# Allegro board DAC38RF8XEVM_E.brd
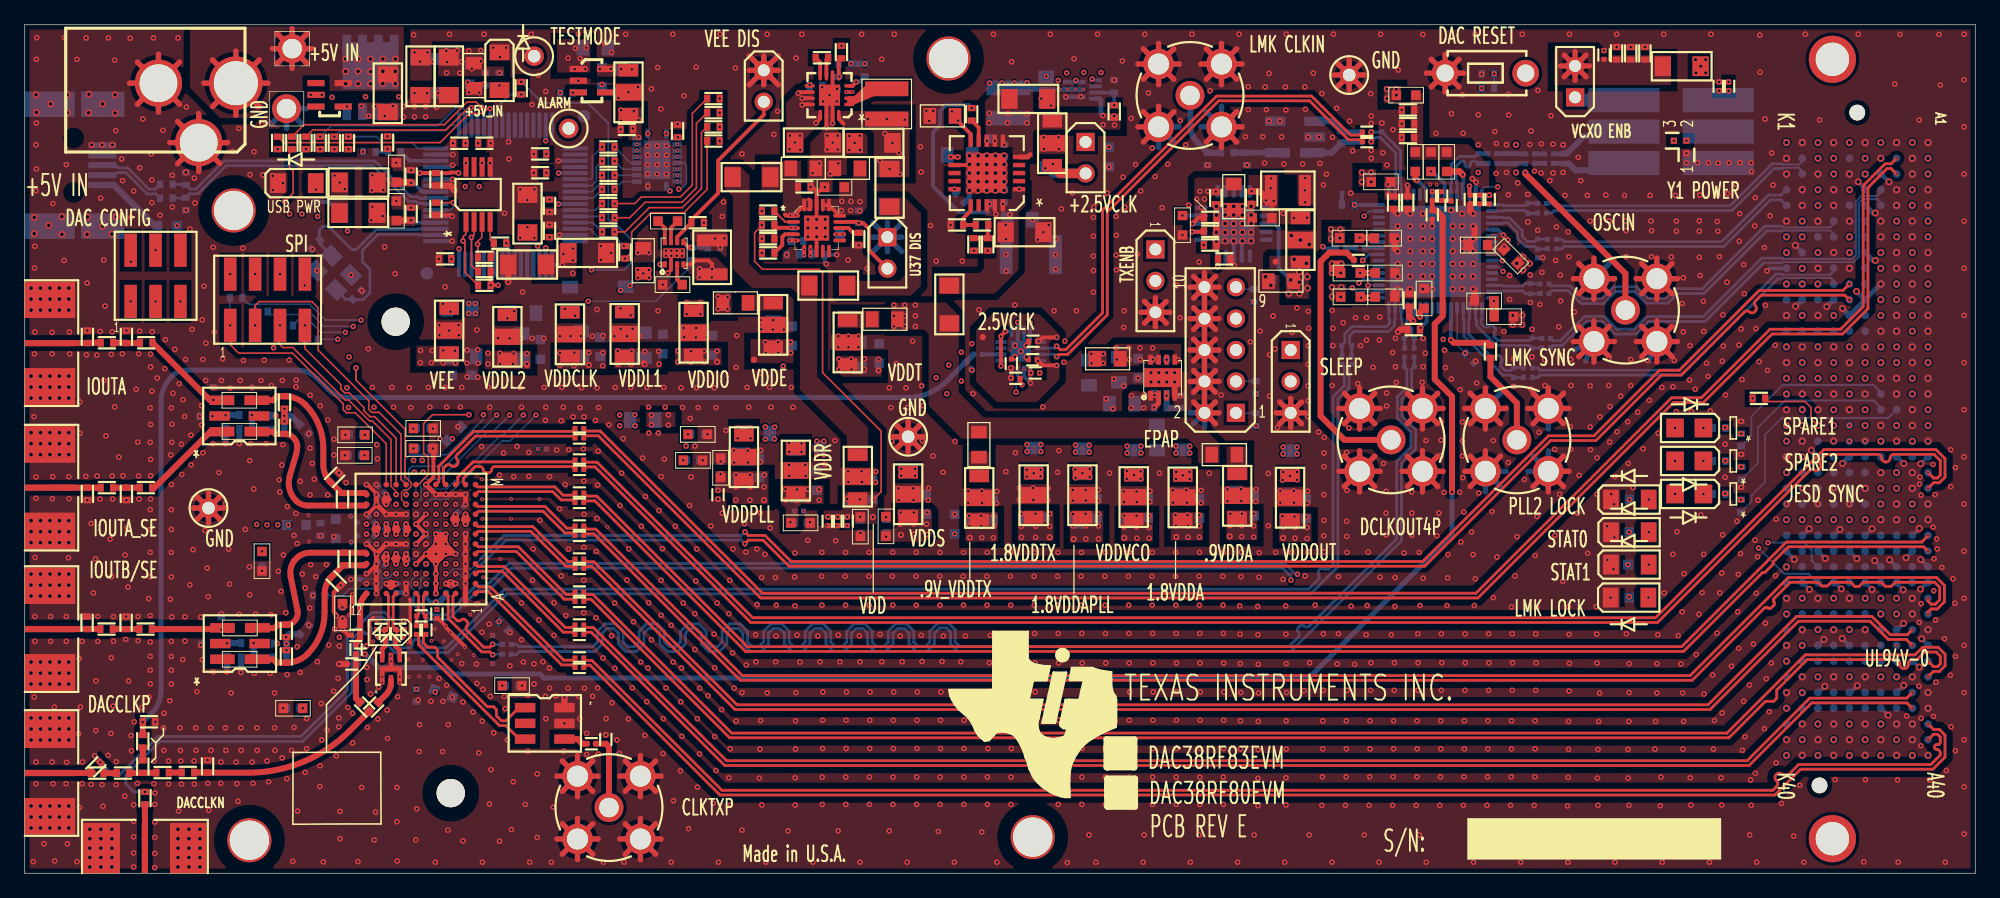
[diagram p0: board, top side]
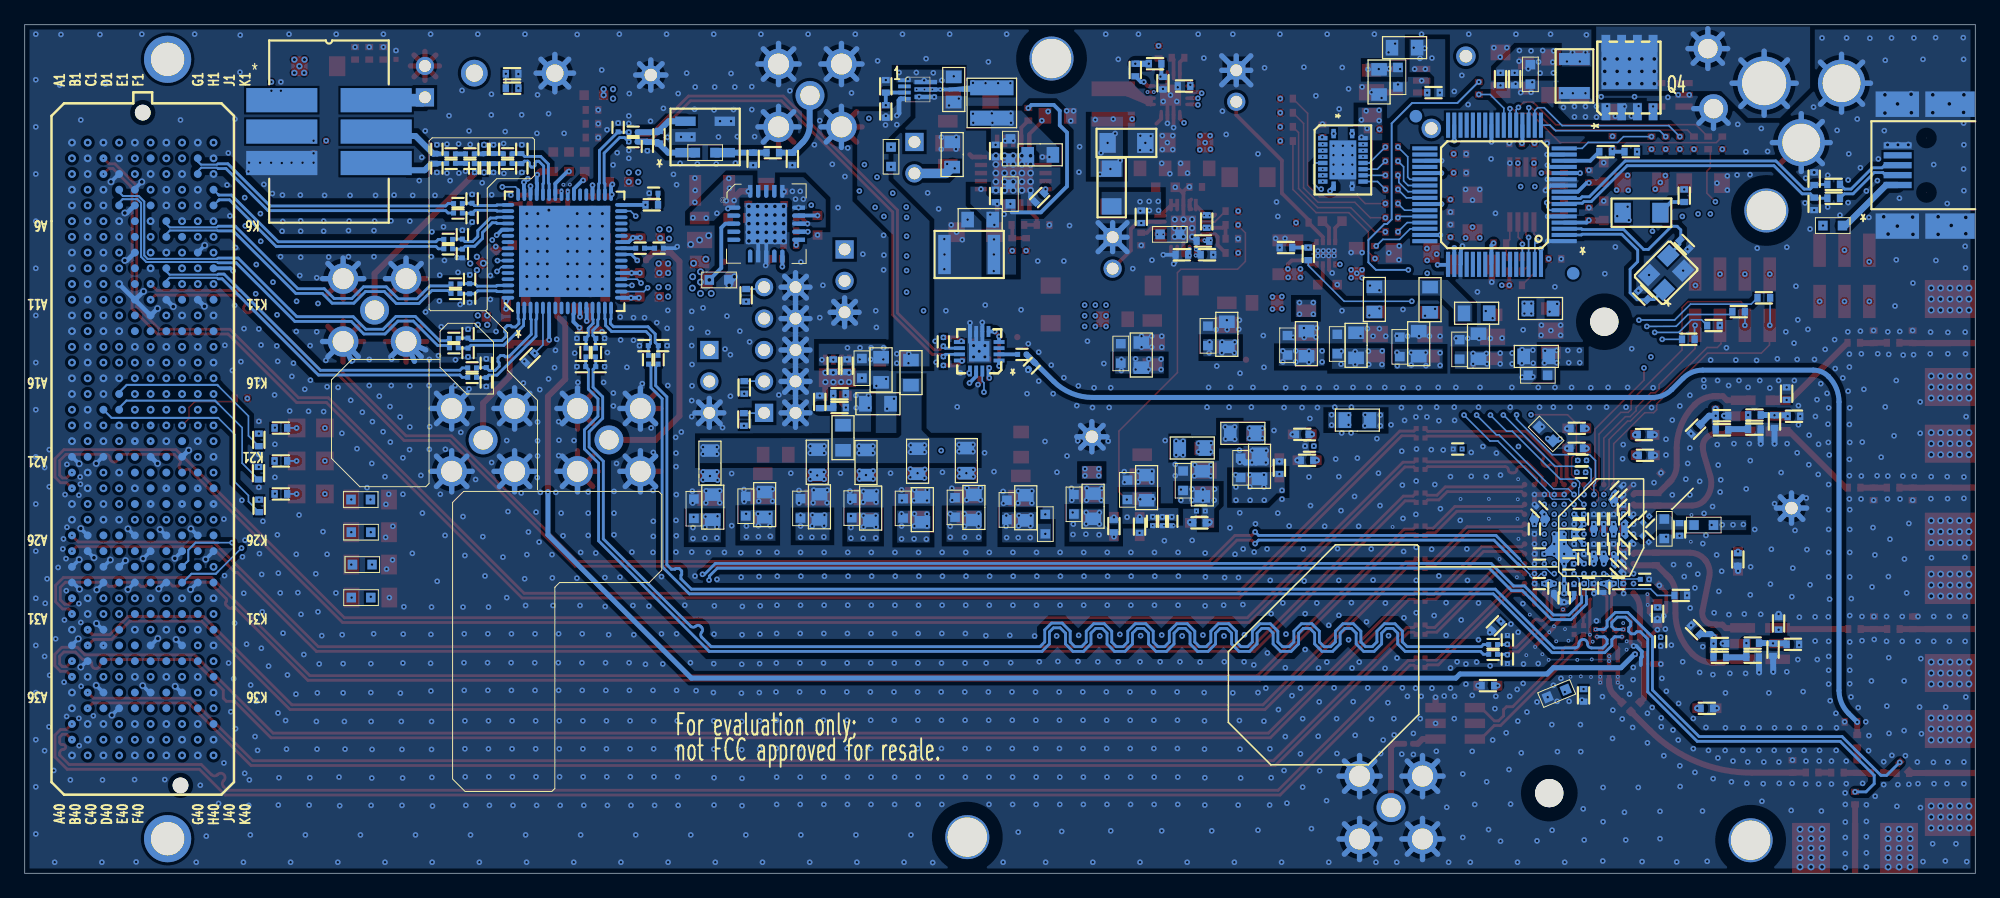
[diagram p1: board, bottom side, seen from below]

Outline 157.48 x 68.58 mm; copper layers: TOP, L2_GND, L3_PWR, L4_SIG, L5_GND, L6_PWR_SIG, L7_GND, BOTTOM. Coordinates in mm from the lower left corner of the outline.
Outline path: 0,68.58 0,0 157.48,0 157.48,68.58 0,68.58

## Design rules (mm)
net group CAR_SYSREF: nets CAR_SYSREFM CAR_SYSREFP
net group CLK: nets CLKN CLKP
net group CLK_LAO: nets CLK_LAO_0M CLK_LAO_0P
net group CLKIN1: nets CLKIN1_N CLKIN1_P
net group DIFFPAIR0: nets DP0_C2M_N_A DP0_C2M_P_A
net group DIFFPAIR1: nets DP7_C2M_N_A DP7_C2M_P_A
net group DIFFPAIR2: nets DP1_C2M_N_A DP1_C2M_P_A
net group DIFFPAIR3: nets DP2_C2M_N_A DP2_C2M_P_A
net group DIFFPAIR4: nets DP3_C2M_N_A DP3_C2M_P_A
net group DIFFPAIR5: nets DP4_C2M_N_A DP4_C2M_P_A
net group DIFFPAIR6: nets DP5_C2M_N_A DP5_C2M_P_A
net group DIFFPAIR7: nets DP6_C2M_N_A DP6_C2M_P_A
net group DIFFPAIR9: nets GTXCLKM GTXCLKP
net group DIFFPAIR12: nets FPGA_CLK1N FPGA_CLK1P
net group DIFFPAIR13: nets FPGA_CLK1_N FPGA_CLK1_P
net group DIFFPAIR14: nets FPGA_CLK2N FPGA_CLK2P
net group DIFFPAIR15: nets FPGA_CLK2_N FPGA_CLK2_P
net group DP1: nets DM DP
net group DP2: nets CLKLA_0M CLKLA_0P
net group DP3: nets CAR_SYSREF_M CAR_SYSREF_P
net group DP4: nets DACCLK_N DACCLK_P
net group DP5: nets SYSREF+ SYSREF-
net group DP6: nets N19086842 N19086844
net group DP7: nets OSCI OSCO
net group DP8: nets N18276385 N18276388
net group DP9: nets N17929635 N17930866
net group DP10: nets N18336017 N18336019
net group DP11: nets N18681043 N18681093
net group DP12: nets N18858975 N18893766
net group GTX_CLK: nets GTX_CLKM GTX_CLKP
net group OSC: nets OSCN OSCP
net group OSCIN: nets OSCINN OSCINP
net group RX0: nets RX0N RX0P
net group RX1: nets RX1N RX1P
net group RX2: nets RX2N RX2P
net group RX3: nets RX3N RX3P
net group RX4: nets RX4N RX4P
net group RX5: nets RX5N RX5P
net group RX6: nets RX6N RX6P
net group RX7: nets RX7N RX7P
net group SYNC0B: nets SYNC0BN SYNC0BP
net group SYNC1B: nets SYNC1BN SYNC1BP
net group SYSREF: nets SYSREFN SYSREFP
net group SYSREF-: nets SYSREF-N SYSREF-P
net group USB_M: nets USB_DM USB_DP
net group Y2: nets Y2_N Y2_P

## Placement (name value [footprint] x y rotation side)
C1  0.01uF  [0402]  28.16 13.43 45 top
C2  .1uF  [0201]  28.77 19.36 45 top
C3  .1uF  [0201]  30.29 19.36 135 top
C5  .1uF  [0201]  44.78 24.64 180 top
C6  .1uF  [0201]  44.78 25.4 180 top
C8  .1uF  [0201]  44.78 19.3 180 top
C9  .1uF  [0201]  44.78 20.07 180 top
C10  .1uF  [0201]  44.78 17.4 180 top
C11  .1uF  [0201]  44.78 16.64 180 top
C13  .1uF  [0201]  44.78 22.73 180 top
C14  .1uF  [0201]  44.78 21.97 180 top
C16  .1uF  [0201]  44.78 27.3 180 top
C17  .1uF  [0201]  44.78 28.07 180 top
C18  .1uF  [0201]  44.78 29.97 180 top
C19  .1uF  [0201]  44.78 30.73 180 top
C21  .1uF  [0201]  44.78 33.4 180 top
C22  .1uF  [0201]  44.78 32.64 180 top
C23  .1uF  [0201]  44.78 35.94 180 top
C24  .1uF  [0201]  44.78 35.18 180 top
C25  0.01uF  [0201]  27.1 17.7 0 top
C27  .001uF  [0402]  118.13 64.62 180 bottom
C28  .1uF  [0201]  26.68 23.76 180 bottom
C29  .1uF  [0201]  122.83 43.23 0 bottom
C30  .68uF  [0402]  106.86 54.03 180 bottom
C31  .1uF  [0201]  136.8 63.6 90 top
C32  .1uF  [0201]  122.83 42.47 0 bottom
C33  3900pF  [0201]  117.47 54.46 270 top
C34  47pF  [0201]  116.71 54.46 270 top
C35  .1uF  [0201]  108.36 59.13 0 bottom
C36  .1uF  [0201]  108.36 59.89 0 bottom
C37  .1uF  [0201]  109.57 60.28 270 bottom
C38  .1uF  [0201]  127.51 66.14 270 top
C39  100pF  [0402]  128.52 66.27 270 top
C40  2200pF  [0402]  129.67 66.27 270 top
C41  10pF  [0402]  130.81 66.27 270 top
C42  .1uF  [0201]  123.29 51.23 0 bottom
C43  .1uF  [0201]  123.29 50.47 0 bottom
C44  .1uF  [0201]  121.54 58.14 180 bottom
C45  .1uF  [0201]  118.49 58.14 180 bottom
C46  .1uF  [0201]  117.35 58.52 270 bottom
C47  .1uF  [0201]  122.5 54.13 0 bottom
C48  .1uF  [0201]  122.5 53.37 0 bottom
C49  .1uF  [0201]  121.54 57.38 180 bottom
C50  .1uF  [0201]  118.49 57.38 180 bottom
C51  12pF  [0201]  117.35 57 90 bottom
C52  1uF  [0402]  110.52 54.2 90 top
C53  .1uF  [0402]  111.66 54.2 90 top
C54  0.01uF  [0402]  112.14 43.94 0 top
C55  1uF  [0603]  109.83 46.58 180 top
C56  1uF  [0603]  109.83 48.51 180 top
C57  1uF  [0603]  109.75 51.33 180 top
C58  1uF  [0402]  111.68 61.7 0 top
C59  .1uF  [0402]  111.68 60.58 0 top
C60  0.01uF  [0402]  111.68 59.46 0 top
C61  .1uF  [0402]  111.79 46.3 90 top
C62  10uF  [0603]  112.98 46.46 90 top
C63  1uF  [0603]  117.32 50.77 0 top
C64  1uF  [0603]  117.83 46.25 0 top
C65  .1uF  [0402]  31.19 56.31 90 top
C66  4.7uF  [0603]  30 56.64 90 top
C67  .1uF  [0402]  31.19 53.29 90 top
C68  4.7uF  [0603]  30 53.54 90 top
C70  10uF  [0805]  46.08 66.73 0 bottom
C71  1.0uF  [0603]  46.61 64.34 270 bottom
C72  10uF  [0805]  48.13 63.96 270 bottom
C73  100uF  [1206]  40.59 53.31 90 top
C74  10uF  [1206]  45.42 50.14 0 top
C75  100uF  [1206]  40.56 49.2 180 top
C76  22pF  [0402]  13 56.13 90 bottom
C77  22pF  [0402]  13 54.1 270 bottom
C78  27pF  [0402]  26.84 46.73 45 bottom
C79  27pF  [0402]  23.49 50.81 225 bottom
C80  .1uF  [0402]  35.08 59 0 top
C81  .1uF  [0402]  42.37 51.92 270 top
C82  .1uF  [0402]  41.61 56.62 0 top
C83  .1uF  [0402]  42.37 53.95 90 top
C84  .1uF  [0402]  33.93 49.66 0 top
C85  .1uF  [0402]  41.61 58.14 0 top
C86  .1uF  [0402]  33.2 56.08 90 top
C87  .1uF  [0402]  37.11 59 180 top
C106  10uF  [0603]  53.95 33.38 0 top
C107  .1uF  [0201]  41.78 34.29 0 bottom
C108  .1uF  [0201]  35.2 29.41 45 bottom
C110  10uF  [0603]  32.17 34.33 0 top
C111  .1uF  [0201]  31.74 33.37 180 bottom
C112  .1uF  [0201]  30.8 28.63 90 bottom
C114  10uF  [0603]  67.46 28.02 270 top
C115  .1uF  [0201]  33.28 20.96 270 top
C116  .1uF  [0201]  66.4 28.45 270 top
C117  .1uF  [0201]  32.81 25 180 bottom
C118  .1uF  [0201]  33.19 22.26 270 bottom
C119  10uF  [0603]  34.65 35.51 45 bottom
C120  1uF  [0201]  32 28.24 180 bottom
C122  .1uF  [0201]  31.6 25.4 90 bottom
C123  .1uF  [0201]  65.63 28.45 270 bottom
C124  .1uF  [0201]  65.63 28.45 270 top
C125  .1uF  [0201]  31.98 29.01 180 bottom
C126  .1uF  [0201]  64.87 28.45 270 bottom
C127  .1uF  [0201]  35.18 25.81 0 bottom
C128  .1uF  [0201]  66.42 28.45 270 bottom
C129  .1uF  [0201]  64.87 28.45 270 top
C131  10uF  [0603]  26.64 33.78 180 top
C132  .1uF  [0201]  29.2 26.99 270 bottom
C133  .1uF  [0201]  29.22 28.63 90 bottom
C135  10uF  [0603]  32.17 35.96 0 top
C136  .1uF  [0201]  30.01 28.63 90 bottom
C137  .1uF  [0201]  31.81 32.41 0 bottom
C139  10uF  [0603]  25.65 21.01 270 top
C140  .1uF  [0201]  28.4 29.4 90 bottom
C141  .1uF  [0201]  28.38 26.21 270 bottom
C143  10uF  [0603]  56.18 32.77 90 top
C144  .1uF  [0201]  55.97 30.59 270 top
C145  .1uF  [0201]  30.8 26.23 90 bottom
C147  10uF  [0603]  19.15 25.22 270 top
C148  .1uF  [0201]  27.99 27.01 225 bottom
C149  .1uF  [0201]  28 28.6 135 bottom
C151  10uF  [0603]  25.11 27.84 270 bottom
C152  .1uF  [0201]  26.61 27.01 225 bottom
C153  .1uF  [0201]  26.57 28.6 135 bottom
C155  10uF  [0603]  21.66 13.34 180 top
C156  .1uF  [0201]  30.01 26.23 90 bottom
C157  .1uF  [0201]  25.4 18.72 270 bottom
C159  10uF  [0603]  33.79 14.53 337.5 bottom
C160  .1uF  [0201]  28.81 23.41 180 bottom
C161  .1uF  [0201]  29.99 23.05 270 bottom
C163  10uF  [0603]  26.67 35.44 180 top
C164  .1uF  [0201]  28.8 25.42 225 bottom
C165  .1uF  [0201]  28.79 31.03 135 bottom
C167  .1uF  [0201]  35.2 23.41 0 bottom
C168  10uF  [0603]  54.34 35.47 0 top
C169  .1uF  [0201]  53.76 34.53 0 bottom
C170  .1uF  [0201]  31.21 23.41 180 bottom
C171  .1uF  [0201]  34.02 23.04 270 bottom
C174  .1uF  [0201]  35.59 27.82 270 bottom
C175  .1uF  [0201]  62.52 29.28 0 bottom
C176  .1uF  [0201]  28.82 24.63 225 bottom
C177  .1uF  [0201]  28.8 30.21 135 bottom
C179  .1uF  [0402]  22.58 19.69 45 bottom
C218  10uF  [0603]  69.53 28.04 90 top
C220  10uF  [0603]  62.64 28.32 0 top
C221  47uF  [1210]  32.36 64.44 90 bottom
C222  10uF  [0805]  36.27 64.47 270 top
C223  .1uF  [0402]  37.19 64.19 90 bottom
C224  22uF  [1206]  31.95 64.41 270 top
C225  1.0uF  [0603]  35.92 64.57 270 bottom
C236  10uF  [0805]  66.9 31.17 90 bottom
C237  1.0uF  [0603]  68.45 30.99 90 bottom
C241  10uF  [0805]  67.34 41.88 90 bottom
C242  1.0uF  [0603]  68.99 42.01 90 bottom
C244  10uF  [0805]  54 42.8 90 bottom
C245  1.0uF  [0603]  55.52 42.67 90 bottom
C247  .1uF  [0402]  79.1 54.74 270 bottom
C248  1.0uF  [0603]  77.9 54.89 90 bottom
C249  33uF  [1812]  81.23 50.01 0 bottom
C250  10uF  [0805]  49.99 42.67 90 bottom
C251  1.0uF  [0603]  51.51 42.77 90 bottom
C253  22uF  [1206]  80.72 51.82 180 top
C254  10uF  [0805]  80.34 52.83 0 bottom
C255  10uF  [0805]  71.22 29.67 90 bottom
C256  1.0uF  [0603]  72.77 29.82 90 bottom
C258  10uF  [0805]  75.49 58.06 0 bottom
C259  1.0uF  [0603]  77.9 58.57 270 bottom
C260  .1uF  [0402]  79.1 58.37 90 bottom
C262  10uF  [0805]  40.11 42.6 90 bottom
C263  1.0uF  [0603]  41.63 42.34 90 bottom
C268  10uF  [0805]  44.93 42.8 90 bottom
C269  1.0uF  [0603]  46.46 42.55 90 bottom
C271  10uF  [0805]  97.74 29.79 90 bottom
C272  1.0uF  [0603]  99.26 29.67 90 bottom
C274  10uF  [0805]  57.79 32.89 90 bottom
C275  1.0uF  [0603]  59.31 32.77 90 bottom
C282  10uF  [0805]  93.32 29.62 90 bottom
C283  1.0uF  [0603]  94.84 29.49 90 bottom
C291  10uF  [0805]  101.93 29.59 90 bottom
C292  1.0uF  [0603]  103.45 29.46 90 bottom
C294  10uF  [0805]  89.18 29.51 90 bottom
C295  1.0uF  [0603]  90.7 29.51 90 bottom
C300  10uF  [0805]  49.94 49.5 90 top
C303  47uF  [1210]  55.5 49.78 90 top
C304  10uF  [0805]  85.01 29.39 90 bottom
C305  1.0uF  [0603]  86.56 29.49 90 bottom
C307  1.0uF  [0603]  51.92 52.7 180 top
C308  10uF  [0805]  62.41 31.47 90 bottom
C309  1.0uF  [0603]  63.96 31.72 90 bottom
C311  10uF  [0805]  97.61 54.69 270 top
C312  .1uF  [0402]  95.71 53.01 180 top
C313  0.01uF  [0402]  96.16 54.58 90 top
C314  .1uF  [0402]  99.06 54.61 270 top
C315  1.0uF  [0603]  99.9 52.96 180 top
C316  47uF  [1210]  101.98 55.19 0 top
C317  10uF  [0805]  101.42 47.85 180 top
C318  1.0uF  [0603]  101.42 47.96 180 bottom
C320  1.0uF  [0603]  93.47 52.37 270 top
C321  1.0uF  [0603]  35.31 40.25 0 bottom
C322  10uF  [0805]  35.44 41.77 0 bottom
C327  5600pF  [0402]  14.72 18.5 180 bottom
C328  .3pF  [0402]  15.88 20.19 90 bottom
C329  5600pF  [0402]  9.75 19.74 180 top
C330  1000pF  [0402]  17.97 18.6 180 bottom
C331  1000pF  [0402]  16.32 18.07 90 bottom
C332  1000pF  [0402]  17.97 17.46 0 bottom
C333  0.01uF  [0201]  29.12 19.36 90 top
C334  0.01uF  [0201]  29.94 19.36 90 top
C342  1uF  [0402]  53.95 33.38 180 bottom
C343  1uF  [0402]  32.17 35.97 180 bottom
C344  1uF  [0402]  56.18 32.77 270 bottom
C345  1uF  [0402]  32.18 34.35 180 bottom
C346  1uF  [0402]  67.47 28.02 90 bottom
C347  1uF  [0402]  26.66 33.78 0 bottom
C348  1uF  [0402]  25.64 20.98 90 bottom
C349  1uF  [0402]  19.17 25.37 90 bottom
C350  1uF  [0402]  23.88 27.79 90 bottom
C351  1uF  [0402]  31.62 14.38 90 bottom
C352  1uF  [0402]  21.67 13.33 0 bottom
C353  1uF  [0402]  54.33 35.48 180 bottom
C356  1uF  [0402]  62.64 28.32 180 bottom
C357  1uF  [0402]  26.75 35.46 0 bottom
C358  1uF  [0402]  69.54 28.06 270 bottom
C360  .1uF  [0201]  113.64 54.74 270 top
C364  .1uF  [0402]  20.62 18.57 0 bottom
C365  .1uF  [0201]  107.67 49.53 180 top
C366  .1uF  [0201]  121.16 57 90 bottom
C368  .1uF  [0402]  48.62 60.12 180 top
C369  .1uF  [0402]  52.71 59.99 270 top
C370  0.01uF  [0402]  27.44 13.44 135 top
C371  .01uF  [0201]  108.36 59.89 0 top
C372  .01uF  [0201]  108.36 59.13 0 top
C373  10uF  [0603]  39.34 15.16 0 top
C374  1uF  [0402]  39.34 15.16 180 bottom
C375  .1uF  [0201]  32.4 22.97 270 bottom
C376  10uF  [0603]  75.08 28.22 90 bottom
C377  1uF  [0402]  38.66 20 135 bottom
C378  .01uF  [0201]  76.96 41.94 0 bottom
C379  .01uF  [0201]  81.58 40.44 0 top
C380  .01uF  [0201]  81.38 41.5 180 top
C381  .01uF  [0201]  79.65 41.2 90 top
C382  .01uF  [0201]  80.01 40.01 0 top
C383  .01uF  [0201]  81.41 43 180 top
C384  22uF  [1206]  63.7 59.05 0 top
C385  0.01uF  [0402]  64.36 65.91 0 top
C386  1.0uF  [0603]  78.18 29.36 90 bottom
C387  10uF  [0805]  76.66 29.54 90 bottom
C388  1.0uF  [0603]  89.89 40.82 270 bottom
C389  .1uF  [0402]  91.08 41.02 90 bottom
C390  10uF  [0805]  88.34 40.69 270 bottom
C391  .047uF  [0402]  92.2 41.02 90 bottom
C392  .047uF  [0402]  91.69 38.76 180 bottom
C393  10uF  [0805]  88.6 37.95 180 bottom
C394  10uF  [0805]  82.47 63.35 270 bottom
C395  22uF  [1206]  81.03 62.59 0 top
C397  5600pF  [0402]  14.63 36.94 180 bottom
C398  .3pF  [0402]  15.23 38.76 90 bottom
C399  5600pF  [0402]  9.8 42.88 180 top
C400  .1uF  [0402]  22.58 35.89 315 bottom
C401  1000pF  [0402]  17.83 37.04 180 bottom
C402  .1uF  [0402]  20.45 36.98 0 bottom
C403  1000pF  [0402]  16.21 36.51 90 bottom
C404  1000pF  [0402]  17.84 35.9 0 bottom
C407  .1uF  [0201]  45.75 10.46 0 top
C413  5600pF  [0402]  9.78 31.17 180 top
C415  10uF  [0805]  74.09 61.21 180 top
C417  1.0uF  [0603]  82.37 29.57 90 bottom
C418  10uF  [0805]  80.85 29.57 90 bottom
C419  1.0uF  [0603]  87.54 57.91 270 bottom
C420  10uF  [0805]  82.6 58.09 90 bottom
C427  0.01uF  [0402]  63.88 63.63 180 bottom
C428  22uF  [1206]  68.53 59.03 180 top
C429  22uF  [1206]  68.53 59.03 180 bottom
C432  1.0uF  [0603]  65.02 51.64 0 bottom
C433  .1uF  [0402]  62.94 55.47 180 top
C434  47uF  [0805]  62.87 56.97 0 top
C435  1.0uF  [0603]  65.38 55.45 180 top
C436  47uF  [0805]  66.42 56.97 180 top
C438  .1uF  [0201]  31.62 19.66 270 top
C439  .1uF  [0201]  32.38 19.66 270 top
C440  0.01uF  [0402]  67.34 51.26 90 top
C441  0.01uF  [0402]  62.05 52.68 90 bottom
C442  4.7uF  [0603]  52.3 47.57 180 top
C443  .1uF  [0201]  114.4 54.74 270 top
C444  1.0uF  [0603]  61.95 43.43 90 bottom
C445  10uF  [0805]  60.43 43.56 90 bottom
C446  .1uF  [0201]  32 26.59 0 bottom
C447  0.01uF  [0402]  75.54 54.61 135 bottom
C448  .1uF  [0201]  107.8 50.52 180 bottom
C449  .1uF  [0201]  30.3 19.71 180 top
C450  .1uF  [0201]  28.77 19.71 0 top
D1  LED GREEN  [LED_1206]  129.59 27.56 180 top
D2  LED GREEN  [LED_1206]  129.59 24.95 180 top
D3  LED GREEN  [LED_1206]  129.57 22.28 180 top
D4  LED GREEN  [LED_1206]  129.59 30.21 180 top
D5  LED AMBER  [LED_1206]  21.97 55.78 180 top
D8  LED BLUE  [LED_0805]  134.39 30.66 0 top
D9  LED BLUE  [LED_0805]  134.39 35.99 0 top
D10  LED BLUE  [LED_0805]  134.39 33.32 0 top
D11  LED GREEN  [LED_1206]  38.33 64.82 90 top
F1  FUSE 2.0A 63V FAST  [1206]  29.31 63.04 270 top
FB1  120 OHM @ 100MHz  [1206]  133.78 65.23 0 top
FB2  120  [0603]  109.5 55.88 0 top
FB3  120  [0603]  107.04 48.51 0 top
FB4  120  [0603]  106.96 51.33 0 top
FB5  120  [0603]  107.04 46.58 0 top
FB6  120  [0603]  111.53 62.89 0 top
FB7  120  [0603]  112.27 57.51 270 top
FB8  120  [0603]  113.54 57.51 270 top
FB9  120  [0603]  114.81 57.51 270 top
FB10  120  [0603]  119.99 49.88 135 top
FB11  120  [0603]  119.43 44.98 180 top
FB12  68 OHM @ 100MHz  [1206]  26.95 55.83 0 top
FB14  68 OHM @ 100MHz  [1206]  26.92 53.37 0 top
FB17  68 OHM @ 100MHz  [1206]  26.95 53.39 0 bottom
FB18  60 OHM @ 100MHz  [1206]  34.24 64.41 270 top
FB19  27uF  [1206_BEAD_NFM31P]  67.26 32.05 270 top
FB20  27uF  [1206_BEAD_NFM31P]  66.45 42.9 270 top
FB21  27uF  [1206_BEAD_NFM31P]  54 43.69 270 top
FB22  27uF  [1206_BEAD_NFM31P]  48.44 43.59 270 top
FB23  27uF  [1206_BEAD_NFM31P]  71.32 30.63 270 top
FB24  27uF  [1206_BEAD_NFM31P]  38.96 43.36 270 top
FB26  27uF  [1206_BEAD_NFM31P]  44.02 43.56 270 top
FB27  27uF  [1206_BEAD_NFM31P]  97.89 30.51 270 top
FB28  27uF  [1206_BEAD_NFM31P]  58.06 33.63 270 top
FB29  27uF  [1206_BEAD_NFM31P]  93.5 30.38 270 top
FB30  27uF  [1206_BEAD_NFM31P]  102.16 30.35 270 top
FB31  27uF  [1206_BEAD_NFM31P]  89.53 30.4 270 top
FB32  27uF  [1206_BEAD_NFM31P]  85.39 30.56 270 top
FB33  27uF  [1206_BEAD_NFM31P]  62.26 32.55 270 top
FB34  27uF  [1206_BEAD_NFM31P]  103 51.18 270 top
FB35  27uF  [1206_BEAD_NFM31P]  34.26 43.87 270 top
FB36  27uF  [1206_BEAD_NFM31P]  48.74 63.12 270 top
FB37  27uF  [1206_BEAD_NFM31P]  77.06 30.33 270 top
FB40  27uF  [1206_BEAD_NFM31P]  82.96 59 270 top
FB41  27uF  [1206_BEAD_NFM31P]  81.46 30.56 90 top
FB42  27uF  [1206_BEAD_NFM31P]  60.43 44.32 270 top
J1  SMA END LAUNCH  [SMA_SMEL_DUAL_PSF-S01_250X215]  0 8.1 90 top
J2  SMA END LAUNCH  [SMA_SMEL_DUAL_PSF-S01_250X215]  0 19.74 90 top
J4  SMA_THVT_REC  [SMA_THVT_312X312]  94.08 62.87 0 top
J6  SMA END LAUNCH  [SMA_SMEL_DUAL_PSF-S01_250X215]  0 42.85 90 top
J7  SMA END LAUNCH  [SMA_SMEL_DUAL_PSF-S01_250X215]  0 31.17 90 top
J8  SMA_THVT_REC  [SMA_THVT_312X312]  120.47 35.03 90 top
J11  HMTSW-105-07-G-D-.240  [HDR_THVT_2X5_100_M]  97.79 37.21 180 top
J16  USB_MINI_AB  [CON_SMRT_USBMINI_AB_F_MOD]  2.54 57.23 0 bottom
J20  CON_SMVT_40x10_SEAM  [CON_SMVT_40X10_SEAM_MTG]  147.95 34.29 90 bottom
J21  CONN JACK PWR  [CON_RAPC722_JACK_THVT_3]  13.92 63.86 270 top
J22  HDR 2X3 2mm  [HDR_SMVT_2X3_79_M]  10.57 48.29 0 top
J23  HDR 2x4 2mm  [HDR_SMVT_2X4_79_M]  19.61 46.36 0 top
J24  SMA_THVT_REC  [SMA_THVT_312X312]  110.31 35.03 0 top
J25  SMA_THVT_REC  [SMA_THVT_312X312]  129.24 45.52 0 top
J26  SMA_THVT_REC  [SMA_THVT_312X312]  47.17 5.31 0 top
J27  SMA END LAUNCH  [SMA_SMEL_DUAL_PSF-S01_250X215]  9.7 0 180 top
JP1  Jumper_1x3_100_430L  [HDR_THVT_1X3_100_M]  102.21 42.29 0 top
JP2  Jumper_1x3_100_430L  [HDR_THVT_1X3_100_M]  91.29 50.42 0 top
JP3  HEADER_1x2_100_430L  [HDR_THVT_1X2_100_M]  125.17 62.71 180 top
JP8  HEADER_1x2_100_430L  [HDR_THVT_1X2_100_M]  69.65 51.41 0 top
JP9  HEADER_1x2_100_430L  [HDR_THVT_1X2_100_M]  59.66 64.9 0 top
JP10  HEADER_1x2_100_430L  [HDR_THVT_1X2_100_M]  85.65 59.11 0 top
L1  560nH  [0402]  21.12 19.59 270 top
L2  560nH  [0402]  21.12 17.53 270 top
L3  1uH  [IND_SM_XFL4015]  69.6 62.18 270 top
L5  .47uH  [IND_SM_XFL4015]  79.4 62.26 270 bottom
L7  560nH  [0402]  20.97 38.05 270 top
L8  560nH  [0402]  20.97 36.02 270 top
L9  560nH  [0402]  20.62 17.45 180 bottom
L10  560nH  [0402]  20.45 35.84 180 bottom
MT1  STANDOFF,  4-40, 3/16 Rd x 1 3/16 Length, ALUM  [MFG125_PLATED]  74.58 65.85 0 top
MT2  STANDOFF,  4-40, 3/16 Rd x 1 3/16 Length, ALUM  [MFG125_PLATED]  18.14 2.67 0 top
MT3  STANDOFF,  4-40, 3/16 Rd x 1 3/16 Length, ALUM  [MFG125_PLATED]  16.87 53.57 0 top
MT4  STANDOFF,  4-40, 3/16 Rd x 1 3/16 Length, ALUM  [MFG125_PLATED]  81.38 2.92 0 top
NOREF  -  []  82.65 4.57 0 top
NOREF#2  -  []  29.95 44.58 90 top
NOREF#3  -  []  116.94 5.84 0 top
NOREF#4  -  []  39.47 3.94 90 top
NOREF#5  -  []  473.3 162.18 0 top
NOREF#6  -  []  81.38 2.92 0 top
NOREF#7  -  []  16.87 53.57 0 top
NOREF#8  -  []  5.08 0 90 top
NOREF#9  -  []  34.39 6.48 90 top
NOREF#10  -  []  91.54 26.8 0 top
NOREF#11  -  []  18.14 2.67 90 top
NOREF#12  -  []  145.95 2.79 90 top
NOREF#13  -  []  18.14 2.67 0 top
NOREF#14  -  []  16.87 53.57 0 top
NOREF#15  -  []  147.95 61.48 90 top
NOREF#16  -  []  35.71 5.59 0 top
NOREF#17  -  []  91.54 24.26 0 top
NOREF#18  -  []  31.85 3.94 0 top
NOREF#19  -  []  31.85 6.22 0 top
NOREF#20  -  []  156.77 0 90 top
NOREF#21  -  []  151.56 -60.71 0 top
NOREF#22  -  []  -116.97 325.27 0 top
NOREF#23  -  []  27.41 20.45 90 top
NOREF#24  -  []  27.41 44.7 0 top
NOREF#25  -  []  17.75 0 90 top
NOREF#26  -  []  -0.03 54.86 0 top
NOREF#27  -  []  27.41 47.12 0 top
NOREF#28  -  []  31.29 45.43 0 top
NOREF#29  -  []  144.91 7.1 0 top
NOREF#30  -  []  16.87 53.57 90 top
NOREF#31  -  [unnamed#2]  34.39 6.48 0 top
NOREF#32  -  []  27.41 33.53 0 top
NOREF#33  -  []  27.99 20.65 0 top
NOREF#34  -  []  82.65 5.84 0 top
NOREF#35  -  []  35.79 3.94 90 top
NOREF#36  -  []  82.65 4.57 90 top
NOREF#37  -  []  116.94 5.84 89.9 top
NOREF#38  -  []  145.95 65.79 0 top
NOREF#39  -  [unnamed#2]  29.95 44.58 0 top
NOREF#40  -  []  0 68.58 0 top
NOREF#41  -  []  125.58 -43.03 0 top
NOREF#42  -  []  144.91 7.1 90 top
NOREF#43  -  []  36.8 12.83 90 top
NOREF#44  -  []  36.64 28.06 0 top
NOREF#45  -  []  220.98 11.43 0 top
NOREF#46  -  []  -10.82 37.72 0 top
NOREF#47  -  []  -0.03 1.78 0 top
NOREF#48  -  []  34.39 6.48 0 top
NOREF#49  -  []  104.85 -24.56 0 top
NOREF#50  -  []  34.39 3.94 90 top
NOREF#51  -  []  91.4 56.79 0 top
NOREF#52  -  []  703.61 127.23 0 top
NOREF#53  -  []  29.95 44.58 90 top
NOREF#54  -  []  74.58 65.85 0 top
NOREF#55  -  []  -127.66 -149.22 0 top
NOREF#56  -  []  94.92 3.91 0 top
NOREF#57  -  []  105.05 11.23 180 bottom
PP1  PROBE POINT  [PROBE_POINT_22PAD]  49.99 41.22 0 top
PP2  PROBE POINT  [PROBE_POINT_22PAD]  40.54 41.07 0 top
PP3  PROBE POINT  [PROBE_POINT_22PAD]  45.54 41.07 0 top
PP4  PROBE POINT  [PROBE_POINT_22PAD]  97.28 27.23 0 top
PP5  PROBE POINT  [PROBE_POINT_22PAD]  59.69 30.15 90 top
PP7  PROBE POINT  [PROBE_POINT_22PAD]  70.74 27.36 270 top
PP8  PROBE POINT  [PROBE_POINT_22PAD]  55.91 41.35 270 top
PP9  PROBE POINT  [PROBE_POINT_22PAD]  68.94 40.64 0 top
PP10  PROBE POINT  [PROBE_POINT_22PAD]  68.48 28.78 270 top
PP13  PROBE POINT  [PROBE_POINT_22PAD]  100.99 49.43 0 top
PP15  PROBE POINT  [PROBE_POINT_22PAD]  34.77 41.25 270 top
PP17  PROBE POINT  [PROBE_POINT_22PAD]  92.96 27.18 0 top
PP18  PROBE POINT  [PROBE_POINT_22PAD]  101.6 27.1 0 top
PP19  PROBE POINT  [PROBE_POINT_22PAD]  88.77 27.1 0 top
PP20  PROBE POINT  [PROBE_POINT_22PAD]  84.68 27 0 top
PP23  PROBE POINT  [PROBE_POINT_22PAD]  64.14 31.01 0 top
PP24  PROBE POINT  [PROBE_POINT_22PAD]  76.3 27.13 0 top
PP25  PROBE POINT  [PROBE_POINT_22PAD]  82.75 27.15 0 top
PP26  PROBE POINT  [PROBE_POINT_22PAD]  77.34 43.33 0 top
PP27  PROBE POINT  [PROBE_POINT_22PAD]  58.88 41.5 0 top
Q1  DTC114EET1G  [SOT_416_3_63X31]  138.58 30.02 180 top
Q2  DTC114EET1G  [SOT_416_3_63X31]  138.58 35.36 180 top
Q3  DTC114EET1G  [SOT_416_3_63X31]  138.58 32.69 180 top
Q4  CSD18532Q5  [SON_Q5B_8]  27.91 64.31 90 bottom
R1  17.8  [0201]  26.75 18.08 270 top
R2  294  [0201]  26.39 16.92 180 top
R3  294  [0201]  26.72 19.23 180 top
R4  49.9  [0201]  37.78 18.86 90 bottom
R5  49.9  [0201]  37.78 17.31 270 bottom
R9  0  [0402]  99.42 36.68 90 bottom
R10  0  [0402]  99.39 39.27 90 bottom
R11  1K  [0402]  118.13 63.45 0 bottom
R12  3.65K  [0402]  23.77 22.45 180 bottom
R20  24.9K  [0201]  137.57 63.6 270 top
R21  39K  [0201]  106.71 54.97 0 bottom
R22  0  [0201]  121.36 40.84 0 bottom
R23  0  [0201]  121.36 40.08 0 bottom
R24  240  [0201]  120.22 39.7 270 bottom
R25  240  [0201]  120.22 41.22 90 bottom
R26  240  [0201]  121.69 42.09 270 bottom
R27  240  [0201]  121.69 43.61 90 bottom
R28  620  [0201]  118.24 54.46 90 top
R29  49.9  [0201]  107.21 58.75 270 bottom
R30  0  [0603]  102.55 58.24 0 bottom
R31  0  [0201]  107.11 41.5 270 bottom
R32  18  [0402]  97.09 58.24 0 bottom
R33  292  [0402]  95.5 57.73 270 bottom
R34  292  [0402]  98.67 57.74 270 bottom
R35  49.9  [0402]  106.27 59.49 90 bottom
R36  0  [0201]  106.35 41.5 270 bottom
R37  240  [0201]  107.49 42.65 0 bottom
R38  240  [0201]  105.97 42.65 180 bottom
R39  100  [0201]  112.17 42.09 270 bottom
R40  100  [0201]  111.4 42.09 270 bottom
R41  240  [0201]  111.02 43.23 180 bottom
R42  240  [0201]  112.55 43.23 0 bottom
R43  130  [0201]  120.4 58.52 270 bottom
R44  100  [0201]  123.06 58.14 180 bottom
R45  240  [0201]  122.15 51.61 90 bottom
R46  240  [0201]  122.15 50.09 270 bottom
R47  82  [0201]  124.21 58.52 90 bottom
R48  49.9  [0201]  119.63 58.52 90 bottom
R49  130  [0201]  120.4 57 90 bottom
R50  240  [0201]  121.36 52.98 270 bottom
R51  240  [0201]  121.36 54.51 90 bottom
R52  100  [0201]  123.06 57.38 180 bottom
R53  82  [0201]  124.21 57 270 bottom
R54  49.9  [0201]  119.63 57 270 bottom
R55  0  [0201]  122.71 47.62 0 bottom
R56  240  [0201]  121.56 48.01 90 bottom
R57  0  [0201]  122.71 46.86 0 bottom
R58  240  [0201]  121.56 46.48 270 bottom
R59  750  [0603]  130.33 27.56 180 bottom
R60  750  [0603]  130.23 24.95 180 bottom
R61  750  [0603]  130.33 22.28 180 bottom
R62  750  [0603]  130.36 30.21 180 bottom
R63  3.01K  [0402]  23.5 54.76 90 bottom
R64  0  [0603]  11.51 52.35 180 bottom
R65  10  [0402]  11.43 54.56 0 bottom
R66  10  [0402]  11.43 55.68 0 bottom
R67  4.7K  [0402]  27.81 58.32 0 bottom
R68  12K  [0402]  33.2 53.7 270 top
R69  1K  [0402]  29.84 58.32 0 bottom
R70  10k  [0402]  29.29 59.05 270 top
R71  10k  [0402]  37.11 47.52 0 top
R72  10k  [0402]  37.11 48.64 0 top
R73  10k  [0402]  38.38 50.93 0 top
R74  2.2K  [0402]  37.11 49.78 0 top
R79  1K  [0402]  136.8 30.66 0 bottom
R80  0  [0402]  138.56 29.69 90 bottom
R81  1K  [0402]  136.8 35.99 0 bottom
R82  0  [0402]  138.58 35.03 90 bottom
R83  0  [0402]  138.61 32.33 90 bottom
R84  1K  [0402]  136.8 33.32 0 bottom
R103  0  [0201]  38.93 18.48 180 bottom
R104  0  [0201]  38.93 17.7 180 bottom
R106  100  [0201]  111.02 40.94 180 bottom
R107  100  [0201]  112.55 40.94 0 bottom
R110  1k  [0402]  38.33 64.19 270 bottom
R115  1.13k  [0402]  77.29 52.4 0 top
R116  4.53k  [0402]  75.26 52.4 180 top
R121  0  [1206]  69.82 55.4 90 top
R122  0  [1206]  64.87 47.5 0 top
R125  255k  [0402]  53.85 50.06 90 bottom
R126  499k  [0402]  55.65 50.57 180 bottom
R129  0  [0402]  95.71 51.89 180 top
R130  0  [0402]  95.71 50.77 180 top
R131  0  [0402]  96.85 49.66 180 top
R140  0  [0402]  43.74 63.09 180 bottom
R148  0  [0402]  118.34 42.16 90 top
R173  22  [0402]  26.14 59.03 90 top
R174  22  [0402]  24.99 59.03 90 top
R175  22  [0402]  23.85 59.03 90 top
R176  22  [0402]  22.71 59.03 90 top
R177  22  [0402]  21.56 59.03 90 top
R178  22  [0402]  20.42 59.03 90 top
R179  0  [0402]  47.12 58.7 180 top
R180  0  [0402]  47.12 57.56 180 top
R181  0  [0402]  47.12 56.41 180 top
R182  0  [0402]  47.12 55.27 180 top
R183  0  [0402]  47.12 54.13 180 top
R184  0  [0402]  47.12 52.98 180 top
R185  0  [0402]  47.12 51.84 180 top
R186  0  [0402]  48.46 50.19 90 top
R187  1.3K  [0402]  116.69 41.66 135 bottom
R199  100  [0402]  25.78 25.4 90 top
R210  11.3  [0402]  11.13 8.14 180 top
R211  11.3  [0402]  7.93 8.1 180 top
R212  71.5  [0402]  9.53 8.62 90 top
R213  .18  [0402]  13.17 8.14 180 top
R214  .18  [0402]  9.53 10.67 90 top
R215  .18  [0402]  5.84 8.09 180 top
R218  49.9  [0201]  83.31 41.4 90 bottom
R219  49.9  [0201]  83.31 42.95 270 bottom
R221  102k  [0402]  66.22 65.43 180 bottom
R222  162k  [0402]  65.58 63.86 270 bottom
R224  10k  [0402]  93.29 38.1 270 bottom
R225  12.7k  [0402]  91.69 37.64 180 bottom
R226  499k  [0402]  67.82 64.92 90 bottom
R227  348k  [0402]  87.96 61.57 90 bottom
R228  162k  [0402]  87.96 63.6 90 bottom
R229  100  [0402]  25.65 30.23 90 top
R232  0  [0402]  140.01 38.38 180 top
R233  22  [0402]  40.08 63.45 90 top
R238  0  [0603]  17.37 19.83 0 top
R239  0  [0402]  25.02 32 45 top
R240  0  [0402]  25.15 23.62 315 top
R241  0  [0603]  17.33 35.71 180 top
R242  49.9  [0402]  14.76 8.64 90 top
R243  49.9  [0201]  76.17 41.02 315 bottom
R244  0  [0402]  99.24 46.71 90 bottom
R248  0  [0603]  17.32 38.23 180 top
R249  0  [0603]  17.35 17.3 0 top
R250  0  [0603]  21.92 28.14 0 bottom
R252  10k  [0402]  76.45 61.34 270 top
R254  1.27K  [0402]  60.02 52.4 0 top
R255  100k  [0402]  60.02 50.14 0 top
R256  10K  [0402]  60.02 51.28 180 top
R258  100k  [0402]  67.34 53.06 270 bottom
R263  0  [0402]  8.2 30.66 270 top
R264  0  [0402]  5.05 30.66 270 top
R265  0  [0402]  8.18 20.24 90 top
R266  0  [0402]  5.03 20.24 90 top
R267  100  [0201]  32 20.8 180 top
R268  0  [0402]  8.2 43.36 90 top
R269  0  [0402]  5.05 43.36 90 top
R272  0  [0402]  6.6 19.74 0 top
R273  0  [0402]  6.63 42.88 0 top
R274  0  [0402]  6.63 31.17 0 top
R280  49.9  [0201]  46.91 10.82 270 top
R282  97.6  [0402]  10.03 12.24 0 top
R283  49.9  [0201]  115.16 53.98 270 top
R284  0  [1206]  58.67 56.26 0 top
R285  100k  [0402]  54.33 52.58 180 top
R286  0  [0402]  60.02 53.52 0 top
R287  49.9  [0201]  113.64 53.21 270 top
R288  0  [0402]  23.16 43.15 0 bottom
R289  0  [0402]  21.13 44.27 0 bottom
R290  0  [0402]  19.1 45.39 0 bottom
R291  0  [0402]  17.07 46.51 0 bottom
R292  0  [0402]  55.6 62.61 0 top
R293  0  [0402]  55.6 61.47 0 top
R294  0  [0402]  55.6 60.33 0 top
R295  0  [0402]  55.6 59.18 0 top
R296  0  [1206]  69.72 55.42 270 bottom
R297  0  [1206]  74.65 45.97 90 top
R298  40.2k  [0402]  65.94 66.37 90 top
R299  0  [0805]  69.44 44.78 0 top
R300  0  [0805]  48.51 46.38 90 bottom
R301  0  [0805]  40.26 45.26 0 bottom
R302  0  [0805]  44.02 46.36 90 bottom
R303  0  [0805]  96.85 33.83 180 top
R304  0  [0805]  59.13 35.56 0 bottom
R305  0  [0805]  77.04 34.65 270 top
R306  0  [0805]  35.1 45.64 0 bottom
R307  0  [0805]  89.56 33.2 90 bottom
R308  0  [0805]  85.39 33.3 90 bottom
R309  0  [0805]  81.46 33.35 90 bottom
R310  0  [0805]  63.22 34.37 0 bottom
R311  0  [0805]  93.5 33.22 90 bottom
R312  0  [0805]  102.16 33.15 90 bottom
R314  0  [0402]  32.9 27.39 0 bottom
R315  0  [0805]  49.89 36.63 180 bottom
R316  0  [0805]  57.38 46.1 180 top
R317  0  [0402]  64.06 49.99 180 bottom
R318  0  [0402]  62.03 49.99 0 bottom
R319  0  [0402]  62.36 51.1 180 bottom
R320  0  [0402]  76.63 50.83 90 top
R321  0  [0402]  77.75 50.83 90 top
R323  0  [0402]  9.7 6.07 270 top
R324  0  [0402]  5.74 8.61 45 top
R329  49.9  [0201]  106.27 50.52 180 bottom
R330  205k  [0402]  87.96 61.57 90 top
R331  0  [0805]  87.43 41.58 180 top
R332  0  [0805]  85.93 40.46 90 bottom
R333  0  [0805]  91.41 35.2 90 bottom
SJP1  SOLDER JUMPER, 0402  [SMD_JUMPER_L_0402]  134.16 58.7 90 top
SW1  DAC RESET  [SW_THVT_SPST_PTS635SL43]  117.93 64.67 0 top
T1  NCR2-113+  [BALUN_6_NCR2]  29.57 16.54 180 top
T3  TC1-1-13M+  [TFMR_5_150X150_50]  102.55 59.51 0 bottom
T5  TCM3-452X-1+  [TFMR_6_160X150_50]  17.37 18.57 180 top
T7  TCM3-452X-1+  [TFMR_6_160X150_50]  17.32 36.96 180 top
T8  TCM2-43X+  [TFMR_6_160X150_50]  41.99 12.12 0 top
TP1  BLK  [TP_THVT_060_RND]  71.32 35.28 0 top
TP2  BLK  [TP_THVT_060_RND]  106.93 64.52 0 top
TP9  YELLOW  [TP_THVT_060_RND]  43.92 60.2 0 top
TP10  YELLOW  [TP_THVT_060_RND]  41.12 66.04 0 top
TP14  BLK  [TP_THVT_060_RND]  14.83 29.51 0 top
TP21  Testloop_Red  [TESTPOINT_62DIA]  21.59 66.65 0 top
TP22  Testloop_Black  [TESTPOINT_62DIA]  21.13 61.8 0 top
U1  DAC38RF80/83 10x10  [BGA_144_10MMX10MM_0P80MM]  31.99 27.01 90 top
U2  LMK04828  [QFN_64_360X360_0P50MM_PWRPAD]  113.89 50.27 90 bottom
U4  FT2232H  [LQFP_64_402X402_20]  38.81 54.84 0 bottom
U5  93LC46B-I/MS  [MSOP_8_118X118_26]  36.6 54.86 90 top
U9  TPS2400  [DBV5]  24.61 62.92 0 top
U12  TPS74401/QFN20  [QFN_20_197X197_0P65_RGW]  77.67 56.59 180 top
U19  LM27761  [SON_DSG_8]  52.43 50.11 90 top
U21  TPS7A4700  [QFN20_RGW_P65PITCH]  97.61 52.5 180 bottom
U23  LP5907-3.3  [DBV5]  45.8 64.06 0 top
U29  TXS0108E  [QFN_20_183X144_RGY]  51.05 57.66 270 bottom
U30  NB7V33M  [QFN_16_124X124_PWRPAD]  80.42 42.19 0 bottom
U31  TPS62095  [QFN_16_124X124_RGT]  64.97 62.89 180 top
U34  TPS7A8101  [SON_DRB_8]  91.87 40.06 90 top
U35  TPS62085  [QFN_RLT_7]  85.39 63.35 180 bottom
U37  TPS7A8500  [QFN20_RGR_P5MM]  63.93 52.15 0 top
Y1  122.88MHz  [VCXO_6_CUSTOM]  132.92 59.94 180 bottom
Y2  12MHz w/ 10pF  [XTAL_4_SM_130X102]  24.96 48.53 135 bottom

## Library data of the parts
C1 C25 C70 C72 C74 C222 C236 C241 C244 C250 C254 C255 C258 C262 C268 C271 C274 C282 C291 C294 C300 C304 C308 C311 C315 C318 C322 C333 C334 C370 C384 C385 C387 C390 C393 C394 C415 C418 C420 C427-C429 C436 C440 C441 C445 C447 = CAP NP_1: tolerance: 10%
C2 C3 C28 C29 C32 C42 C43 C46-C48 C52-C61 C63 C64 C80-C87 C179 C223 C247 C260 C312 C313 C327 C329-C332 C342-C353 C356-C358 C360 C364-C366 C368 C369 C374 C377 C389 C391 C392 C397 C399-C404 C413 C432 C433 C443 C448 = CAPACITOR_NP_1: tolerance: 10%
C5 C6 C8-C11 C13 C14 C16-C19 C21-C24 C107 C108 C111 C112 C115-C118 C122-C129 C132 C133 C136 C137 C140 C141 C144 C145 C148 C149 C152 C153 C156 C157 C160 C161 C164 C165 C167 C169-C171 C174-C177 C375 C407 C438 C439 C446 C449 C450 = CAP0402_0: tolerance: 10%
C27 = CAP_0402_0.001uF_H
C30 C31 C33 C45 C50 C66 C68 C71 C221 C225 C237 C242 C245 C248 C251 C256 C259 C263 C269 C272 C275 C283 C292 C295 C303 C305 C307 C309 C320 C321 C386 C388 C417 C419 C434 C435 C442 C444 = CAP NP_0: tolerance: 10%
C34 = CAP NP_0: tolerance: 5%
C35 C36 C371 C372 C378-C383 = CAP_0402_0.01uF_H: tolerance: 10%
C37 = CAP_0402_0.1uF: tolerance: 10%
C38 C44 C49 = CAP_0402_0.1uF_H: tolerance: 10%
C39 = CAP_0603_100pF_H
C40 = CAP_0402_2200pF_H
C41 = CAP_0402_10pF_H
C51 = CAPACITOR_NP_1: tolerance: 2%
C62 = CAP NP_2: tolerance: 10%
C65 C67 C314 = CAP0603: tolerance: 10%
C73 C75 = CAP_1206
C76 C77 = CAP NP: tolerance: 10%
C78 C79 = CAP NP: tolerance: 5%
C106 C110 C114 C119 C131 C135 C139 C143 C147 C151 C155 C159 C163 C168 C218 C220 C317 C373 C376 = CAP0201_0: tolerance: 20%
C120 = CAPACITOR_NP_1: tolerance: 20%
C224 C253 = CAP_1210_22uF
C249 = CAP NP_1: tolerance: 20%
C316 = CAP0201_0: tolerance: 10%
C328 C398 = CAPACITOR_NP_1: tolerance: .05pF
C395 = CAP: tolerance: 10%
D1-D4 D8-D10 = LED
D5 = LED_AMBER_1206
D11 = LED_GREEN_1206
F1 = FUSE_0
FB1-FB11 = FERRITE_BEAD_0402_H
FB12 FB14 FB17 FB18 = FERRITE_BEAD
FB19-FB24 FB26-FB37 FB40-FB42 = BEAD_NFM31P
J1 J2 J6 J7 J27 = TMP_122841
J4 J8 J24-J26 = SMA-THVT_142-0701-201_REC
J11 = HEADER_2x5_100
J16 = USB_MINI_AB_MNE20-5G5P10
J20 = CON_SMVT_40X10_ASP-134487-01
J21 = CONN JACK PWR
J22 = HEADER_2x3_100
J23 = HEADER_2x4_100
JP1 JP2 = Jumper_1x3_100_0
JP3 JP10 = HDR_2x1_100
JP8 JP9 = JUMPER_1x2_0
L1-L3 L5 L7-L10 = CHOKE
MT1-MT4 = MOUNTING_HOLE
PP1-PP5 PP7-PP10 PP13 PP15 PP17-PP20 PP23-PP27 = PROBE_POINT_0
Q1-Q3 = MMBT2222A
Q4 = CSD18532Q5B
R1-R3 R210-R215 = RES0603: tolerance: 1%
R4 R5 R35 R242 R243 R282 = Res_0402_49.9
R9 R10 R65 R66 R173-R186 R272-R274 R289-R295 = Res_0402_10_H
R11 R69-R73 R252 R254 = R_0: tolerance: 1%
R12 = Res_0402_1.8K
R20 = Res_0402_24.9
R21 R28 R224 R225 R258 R285 = R_1: tolerance: 1%
R22 R23 R31 R36 R39 R40 R55 R57 R121 R122 R267 R284 R296 R297 R299-R312 R315 R316 R331-R333 = Res_0402_Zero_H_DNI
R24-R27 R37 R38 R41 R42 R45 R46 R50 R51 R56 R58 = Res_0402_249
R29 R280 R283 R287 R329 = Res_0402_49.9: tolerance: 1%
R30 R250 = Res_0603_Zero_DNI
R32 = Res_0402_18
R33 R34 = Res_0402_270
R43 R47-R49 R53 R54 R218 R219 = RESISTOR_0: tolerance: 1%
R44 R52 R199 R229 = Res_0402_100_H
R59-R62 R187 = RESISTOR_0
R63 R103 R104 R129-R131 R140 R148 R238-R241 R244 R248 R249 R263-R266 R268 R269 R286 R314 R317-R319 = R: tolerance: 5%
R64 = Res_0402_Zero
R67 R74 = RESISTOR
R68 R79 R81 R84 R115 R116 R222 R228 R255 = R: tolerance: 1%
R80 R82 R83 R125 R126 R221 R226 R227 R232 R233 R298 R330 = Res_0603_Zero_H
R106 R107 = Res_0603_100
R110 = Res_0402_1k
R256 = RESISTOR: tolerance: 1%
R288 R323 R324 = Res_0402_10_H: tolerance: 5%
R320 R321 = Res_0402_Zero_H_DNI: tolerance: 5%
SJP1 = SMD_JUMPER_1x3
SW1 = SW PUSHBUTTON
T1 = BALUN_NCR2-113+
T3 = TFMR_5_TC1-1-13M+
T5 T7 = TFMR_6_TCM3-452X+
T8 = TFMR_6_TCM2-43X+
TP1 TP2 TP14 = TESTPOINT_BLK
TP9 TP10 = TESTPOINT_BLUE
TP21 TP22 = TESTLOOP_BLACK
U1 = DAC38RF80_10x10
U2 = LMK04828
U4 = FT4232H_2
U5 = EEPROM
U9 = TPS2400
U12 = TPS74401/QFN20
U19 = LM27761
U21 = TPS7A4700
U23 = LP5907
U29 = TXS0108E
U30 = NB7V33M
U31 = TPS62095
U34 = TPS7A8101
U35 = TPS62085/62086/62087
U37 = TPS7A8500
Y1 = OSC_SM_6_TCO-2100-SERIES_2
Y2 = CRYSTAL1-4/SM

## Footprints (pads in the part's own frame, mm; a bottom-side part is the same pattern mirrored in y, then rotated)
0201
  rect 0.406x0.406 smd: 1(-0.356,0) 2(0.356,0)
0402
  rect 0.508x0.635 smd: 1(-0.508,0) 2(0.508,0)
0603
  rect 0.762x0.787 smd: 1(-0.787,0) 2(0.787,0)
0805
  rect 1.016x1.27 smd: 1(-1.016,0) 2(1.016,0)
1206
  rect 1.321x1.6 smd: 1(-1.524,0) 2(1.524,0)
1206_BEAD_NFM31P
  rect 1.016x1.575 smd: 1(-1.778,0) 3(1.778,0)
  rect 1.321x2.032 smd: 2(0,0)
1210
  rect 0.965x2.489 smd: 1(-1.372,0) 2(1.372,0)
1812
  rect 1.016x3.175 smd: 1(-1.994,0) 2(1.994,0)
BALUN_6_NCR2
  rect 0.356x0.762 smd: 1(0.71,0.89) 2(0,0.89) 3(-0.71,0.89) 4(-0.71,-0.89) 5(0,-0.89) 6(0.71,-0.89)
BGA_144_10MMX10MM_0P80MM
  round 0.457 smd: A1(-4.4,-4.4) A2(-4.4,-3.6) A3(-4.4,-2.8) A4(-4.4,-2) A5(-4.4,-1.2) A6(-4.4,-0.4) A7(-4.4,0.4) A8(-4.4,1.2) A9(-4.4,2) A10(-4.4,2.8) A11(-4.4,3.6) A12(-4.4,4.4) B1(-3.6,-4.4) B2(-3.6,-3.6) B3(-3.6,-2.8) B4(-3.6,-2) B5(-3.6,-1.2) B6(-3.6,-0.4) B7(-3.6,0.4) B8(-3.6,1.2) B9(-3.6,2) B10(-3.6,2.8) B11(-3.6,3.6) B12(-3.6,4.4) C1(-2.8,-4.4) C2(-2.8,-3.6) C3(-2.8,-2.8) C4(-2.8,-2) C5(-2.8,-1.2) C6(-2.8,-0.4) C7(-2.8,0.4) C8(-2.8,1.2) C9(-2.8,2) C10(-2.8,2.8) C11(-2.8,3.6) C12(-2.8,4.4) D1(-2,-4.4) D2(-2,-3.6) D3(-2,-2.8) D4(-2,-2) D5(-2,-1.2) D6(-2,-0.4) D7(-2,0.4) D8(-2,1.2) D9(-2,2) D10(-2,2.8) D11(-2,3.6) D12(-2,4.4) E1(-1.2,-4.4) E2(-1.2,-3.6) E3(-1.2,-2.8) E4(-1.2,-2) E5(-1.2,-1.2) E6(-1.2,-0.4) E7(-1.2,0.4) E8(-1.2,1.2) E9(-1.2,2) E10(-1.2,2.8) E11(-1.2,3.6) E12(-1.2,4.4) F1(-0.4,-4.4) F2(-0.4,-3.6) F3(-0.4,-2.8) F4(-0.4,-2) F5(-0.4,-1.2) F6(-0.4,-0.4) F7(-0.4,0.4) F8(-0.4,1.2) F9(-0.4,2) F10(-0.4,2.8) F11(-0.4,3.6) F12(-0.4,4.4) G1(0.4,-4.4) G2(0.4,-3.6) G3(0.4,-2.8) G4(0.4,-2) G5(0.4,-1.2) G6(0.4,-0.4) G7(0.4,0.4) G8(0.4,1.2) G9(0.4,2) G10(0.4,2.8) G11(0.4,3.6) G12(0.4,4.4) H1(1.2,-4.4) H2(1.2,-3.6) H3(1.2,-2.8) H4(1.2,-2) H5(1.2,-1.2) H6(1.2,-0.4) H7(1.2,0.4) H8(1.2,1.2) H9(1.2,2) H10(1.2,2.8) H11(1.2,3.6) H12(1.2,4.4) J1(2,-4.4) J2(2,-3.6) J3(2,-2.8) J4(2,-2) J5(2,-1.2) J6(2,-0.4) J7(2,0.4) J8(2,1.2) J9(2,2) J10(2,2.8) J11(2,3.6) J12(2,4.4) K1(2.8,-4.4) K2(2.8,-3.6) K3(2.8,-2.8) K4(2.8,-2) K5(2.8,-1.2) K6(2.8,-0.4) K7(2.8,0.4) K8(2.8,1.2) K9(2.8,2) K10(2.8,2.8) K11(2.8,3.6) K12(2.8,4.4) L1(3.6,-4.4) L2(3.6,-3.6) L3(3.6,-2.8) L4(3.6,-2) L5(3.6,-1.2) L6(3.6,-0.4) L7(3.6,0.4) L8(3.6,1.2) L9(3.6,2) L10(3.6,2.8) L11(3.6,3.6) L12(3.6,4.4) M1(4.4,-4.4) M2(4.4,-3.6) M3(4.4,-2.8) M4(4.4,-2) M5(4.4,-1.2) M6(4.4,-0.4) M7(4.4,0.4) M8(4.4,1.2) M9(4.4,2) M10(4.4,2.8) M11(4.4,3.6) M12(4.4,4.4)
CON_RAPC722_JACK_THVT_3
  round 4.318 hole 3.556: 1(0,3.124)
  round 3.81 hole 3.048: 2(0,-3.124) 3(4.801,0.127)
CON_SMRT_USBMINI_AB_F_MOD
  round 0.025 hole 0.9 unplated: (1.4,-2.2) (1.4,2.2)
  rect 2.261x0.508 smd: 1(3.725,1.6) 2(3.725,0.8) 3(3.725,0) 4(3.725,-0.8) 5(3.725,-1.6)
  rect 3.988x2.057 smd: 6(-0.5,4.92) 9(-0.5,-4.93)
  rect 3.505x2.057 smd: 7(3.75,4.92) 8(3.75,-4.93)
CON_SMVT_40X10_SEAM_MTG
  round 3.81 hole 2.692: (-31.496,-2.007) (31.496,-2.007)
  round 1.27 hole 1.27 unplated: (-27.191,-3.048) (27.191,0)
  round 0.635 smd: A1(24.765,5.715) A2(23.495,5.715) A3(22.225,5.715) A4(20.955,5.715) A5(19.685,5.715) A6(18.415,5.715) A7(17.145,5.715) A8(15.875,5.715) A9(14.605,5.715) A10(13.335,5.715) A11(12.065,5.715) A12(10.795,5.715) A13(9.525,5.715) A14(8.255,5.715) A15(6.985,5.715) A16(5.715,5.715) A17(4.445,5.715) A18(3.175,5.715) A19(1.905,5.715) A20(0.635,5.715) A21(-0.635,5.715) A22(-1.905,5.715) A23(-3.175,5.715) A24(-4.445,5.715) A25(-5.715,5.715) A26(-6.985,5.715) A27(-8.255,5.715) A28(-9.525,5.715) A29(-10.795,5.715) A30(-12.065,5.715) A31(-13.335,5.715) A32(-14.605,5.715) A33(-15.875,5.715) A34(-17.145,5.715) A35(-18.415,5.715) A36(-19.685,5.715) A37(-20.955,5.715) A38(-22.225,5.715) A39(-23.495,5.715) A40(-24.765,5.715) B1(24.765,4.445) B2(23.495,4.445) B3(22.225,4.445) B4(20.955,4.445) B5(19.685,4.445) B6(18.415,4.445) B7(17.145,4.445) B8(15.875,4.445) B9(14.605,4.445) B10(13.335,4.445) B11(12.065,4.445) B12(10.795,4.445) B13(9.525,4.445) B14(8.255,4.445) B15(6.985,4.445) B16(5.715,4.445) B17(4.445,4.445) B18(3.175,4.445) B19(1.905,4.445) B20(0.635,4.445) B21(-0.635,4.445) B22(-1.905,4.445) B23(-3.175,4.445) B24(-4.445,4.445) B25(-5.715,4.445) B26(-6.985,4.445) B27(-8.255,4.445) B28(-9.525,4.445) B29(-10.795,4.445) B30(-12.065,4.445) B31(-13.335,4.445) B32(-14.605,4.445) B33(-15.875,4.445) B34(-17.145,4.445) B35(-18.415,4.445) B36(-19.685,4.445) B37(-20.955,4.445) B38(-22.225,4.445) B39(-23.495,4.445) B40(-24.765,4.445) C1(24.765,3.175) C2(23.495,3.175) C3(22.225,3.175) C4(20.955,3.175) C5(19.685,3.175) C6(18.415,3.175) C7(17.145,3.175) C8(15.875,3.175) C9(14.605,3.175) C10(13.335,3.175) C11(12.065,3.175) C12(10.795,3.175) C13(9.525,3.175) C14(8.255,3.175) C15(6.985,3.175) C16(5.715,3.175) C17(4.445,3.175) C18(3.175,3.175) C19(1.905,3.175) C20(0.635,3.175) C21(-0.635,3.175) C22(-1.905,3.175) C23(-3.175,3.175) C24(-4.445,3.175) C25(-5.715,3.175) C26(-6.985,3.175) C27(-8.255,3.175) C28(-9.525,3.175) C29(-10.795,3.175) C30(-12.065,3.175) C31(-13.335,3.175) C32(-14.605,3.175) C33(-15.875,3.175) C34(-17.145,3.175) C35(-18.415,3.175) C36(-19.685,3.175) C37(-20.955,3.175) C38(-22.225,3.175) C39(-23.495,3.175) C40(-24.765,3.175) D1(24.765,1.905) D2(23.495,1.905) D3(22.225,1.905) D4(20.955,1.905) D5(19.685,1.905) D6(18.415,1.905) D7(17.145,1.905) D8(15.875,1.905) D9(14.605,1.905) D10(13.335,1.905) D11(12.065,1.905) D12(10.795,1.905) D13(9.525,1.905) D14(8.255,1.905) D15(6.985,1.905) D16(5.715,1.905) D17(4.445,1.905) D18(3.175,1.905) D19(1.905,1.905) D20(0.635,1.905) D21(-0.635,1.905) D22(-1.905,1.905) D23(-3.175,1.905) D24(-4.445,1.905) D25(-5.715,1.905) D26(-6.985,1.905) D27(-8.255,1.905) D28(-9.525,1.905) D29(-10.795,1.905) D30(-12.065,1.905) D31(-13.335,1.905) D32(-14.605,1.905) D33(-15.875,1.905) D34(-17.145,1.905) D35(-18.415,1.905) D36(-19.685,1.905) D37(-20.955,1.905) D38(-22.225,1.905) D39(-23.495,1.905) D40(-24.765,1.905) E1(24.765,0.635) E2(23.495,0.635) E3(22.225,0.635) E4(20.955,0.635) E5(19.685,0.635) E6(18.415,0.635) E7(17.145,0.635) E8(15.875,0.635) E9(14.605,0.635) E10(13.335,0.635) E11(12.065,0.635) E12(10.795,0.635) E13(9.525,0.635) E14(8.255,0.635) E15(6.985,0.635) E16(5.715,0.635) E17(4.445,0.635) E18(3.175,0.635) E19(1.905,0.635) E20(0.635,0.635) E21(-0.635,0.635) E22(-1.905,0.635) E23(-3.175,0.635) E24(-4.445,0.635) E25(-5.715,0.635) E26(-6.985,0.635) E27(-8.255,0.635) E28(-9.525,0.635) E29(-10.795,0.635) E30(-12.065,0.635) E31(-13.335,0.635) E32(-14.605,0.635) E33(-15.875,0.635) E34(-17.145,0.635) E35(-18.415,0.635) E36(-19.685,0.635) E37(-20.955,0.635) E38(-22.225,0.635) E39(-23.495,0.635) E40(-24.765,0.635) F1(24.765,-0.635) F2(23.495,-0.635) F3(22.225,-0.635) F4(20.955,-0.635) F5(19.685,-0.635) F6(18.415,-0.635) F7(17.145,-0.635) F8(15.875,-0.635) F9(14.605,-0.635) F10(13.335,-0.635) F11(12.065,-0.635) F12(10.795,-0.635) F13(9.525,-0.635) F14(8.255,-0.635) F15(6.985,-0.635) F16(5.715,-0.635) F17(4.445,-0.635) F18(3.175,-0.635) F19(1.905,-0.635) F20(0.635,-0.635) F21(-0.635,-0.635) F22(-1.905,-0.635) F23(-3.175,-0.635) F24(-4.445,-0.635) F25(-5.715,-0.635) F26(-6.985,-0.635) F27(-8.255,-0.635) F28(-9.525,-0.635) F29(-10.795,-0.635) F30(-12.065,-0.635) F31(-13.335,-0.635) F32(-14.605,-0.635) F33(-15.875,-0.635) F34(-17.145,-0.635) F35(-18.415,-0.635) F36(-19.685,-0.635) F37(-20.955,-0.635) F38(-22.225,-0.635) F39(-23.495,-0.635) F40(-24.765,-0.635) G1(24.765,-1.905) G2(23.495,-1.905) G3(22.225,-1.905) G4(20.955,-1.905) G5(19.685,-1.905) G6(18.415,-1.905) G7(17.145,-1.905) G8(15.875,-1.905) G9(14.605,-1.905) G10(13.335,-1.905) G11(12.065,-1.905) G12(10.795,-1.905) G13(9.525,-1.905) G14(8.255,-1.905) G15(6.985,-1.905) G16(5.715,-1.905) G17(4.445,-1.905) G18(3.175,-1.905) G19(1.905,-1.905) G20(0.635,-1.905) G21(-0.635,-1.905) G22(-1.905,-1.905) G23(-3.175,-1.905) G24(-4.445,-1.905) G25(-5.715,-1.905) G26(-6.985,-1.905) G27(-8.255,-1.905) G28(-9.525,-1.905) G29(-10.795,-1.905) G30(-12.065,-1.905) G31(-13.335,-1.905) G32(-14.605,-1.905) G33(-15.875,-1.905) G34(-17.145,-1.905) G35(-18.415,-1.905) G36(-19.685,-1.905) G37(-20.955,-1.905) G38(-22.225,-1.905) G39(-23.495,-1.905) G40(-24.765,-1.905) H1(24.765,-3.175) H2(23.495,-3.175) H3(22.225,-3.175) H4(20.955,-3.175) H5(19.685,-3.175) H6(18.415,-3.175) H7(17.145,-3.175) H8(15.875,-3.175) H9(14.605,-3.175) H10(13.335,-3.175) H11(12.065,-3.175) H12(10.795,-3.175) H13(9.525,-3.175) H14(8.255,-3.175) H15(6.985,-3.175) H16(5.715,-3.175) H17(4.445,-3.175) H18(3.175,-3.175) H19(1.905,-3.175) H20(0.635,-3.175) H21(-0.635,-3.175) H22(-1.905,-3.175) H23(-3.175,-3.175) H24(-4.445,-3.175) H25(-5.715,-3.175) H26(-6.985,-3.175) H27(-8.255,-3.175) H28(-9.525,-3.175) H29(-10.795,-3.175) H30(-12.065,-3.175) H31(-13.335,-3.175) H32(-14.605,-3.175) H33(-15.875,-3.175) H34(-17.145,-3.175) H35(-18.415,-3.175) H36(-19.685,-3.175) H37(-20.955,-3.175) H38(-22.225,-3.175) H39(-23.495,-3.175) H40(-24.765,-3.175) J1(24.765,-4.445) J2(23.495,-4.445) J3(22.225,-4.445) J4(20.955,-4.445) J5(19.685,-4.445) J6(18.415,-4.445) J7(17.145,-4.445) J8(15.875,-4.445) J9(14.605,-4.445) J10(13.335,-4.445) J11(12.065,-4.445) J12(10.795,-4.445) J13(9.525,-4.445) J14(8.255,-4.445) J15(6.985,-4.445) J16(5.715,-4.445) J17(4.445,-4.445) J18(3.175,-4.445) J19(1.905,-4.445) J20(0.635,-4.445) J21(-0.635,-4.445) J22(-1.905,-4.445) J23(-3.175,-4.445) J24(-4.445,-4.445) J25(-5.715,-4.445) J26(-6.985,-4.445) J27(-8.255,-4.445) J28(-9.525,-4.445) J29(-10.795,-4.445) J30(-12.065,-4.445) J31(-13.335,-4.445) J32(-14.605,-4.445) J33(-15.875,-4.445) J34(-17.145,-4.445) J35(-18.415,-4.445) J36(-19.685,-4.445) J37(-20.955,-4.445) J38(-22.225,-4.445) J39(-23.495,-4.445) J40(-24.765,-4.445) K1(24.765,-5.715) K2(23.495,-5.715) K3(22.225,-5.715) K4(20.955,-5.715) K5(19.685,-5.715) K6(18.415,-5.715) K7(17.145,-5.715) K8(15.875,-5.715) K9(14.605,-5.715) K10(13.335,-5.715) K11(12.065,-5.715) K12(10.795,-5.715) K13(9.525,-5.715) K14(8.255,-5.715) K15(6.985,-5.715) K16(5.715,-5.715) K17(4.445,-5.715) K18(3.175,-5.715) K19(1.905,-5.715) K20(0.635,-5.715) K21(-0.635,-5.715) K22(-1.905,-5.715) K23(-3.175,-5.715) K24(-4.445,-5.715) K25(-5.715,-5.715) K26(-6.985,-5.715) K27(-8.255,-5.715) K28(-9.525,-5.715) K29(-10.795,-5.715) K30(-12.065,-5.715) K31(-13.335,-5.715) K32(-14.605,-5.715) K33(-15.875,-5.715) K34(-17.145,-5.715) K35(-18.415,-5.715) K36(-19.685,-5.715) K37(-20.955,-5.715) K38(-22.225,-5.715) K39(-23.495,-5.715) K40(-24.765,-5.715)
DBV5
  rect 1.4x0.5 smd: 1(-1.1,0.95) 2(-1.1,0) 3(-1.1,-0.95) 4(1.1,-0.95) 5(1.1,0.95)
HDR_SMVT_2X3_79_M
  rect 1.016x2.692 smd: 1(-2.018,-2.07) 2(-2.018,2.07) 3(-0.009,-2.07) 4(-0.009,2.07) 5(2,-2.07) 6(2,2.07)
HDR_SMVT_2X4_79_M
  rect 1.016x2.692 smd: 1(-3.018,-2.07) 2(-3.018,2.07) 3(-1.009,-2.07) 4(-1.009,2.07) 5(1,-2.07) 6(1,2.07) 7(3.009,-2.07) 8(3.009,2.07)
HDR_THVT_1X2_100_M
  rect 1.473x1.473 hole 0.965: 1(0,0)
  round 1.473 hole 0.965: 2(0,-2.54)
HDR_THVT_1X3_100_M
  rect 1.473x1.473 hole 0.965: 1(0,0)
  round 1.473 hole 0.965: 2(0,-2.54) 3(0,-5.08)
HDR_THVT_2X5_100_M
  rect 1.473x1.473 hole 0.965: 1(0,0)
  round 1.473 hole 0.965: 2(2.54,0) 3(0,-2.54) 4(2.54,-2.54) 5(0,-5.08) 6(2.54,-5.08) 7(0,-7.62) 8(2.54,-7.62) 9(0,-10.16) 10(2.54,-10.16)
IND_SM_XFL4015
  rect 1.2x3.5 smd: 1(-1.225,0) 2(1.225,0)
LED_0805
  rect 1.422x1.524 smd: 1(-1.143,0) 2(1.143,0)
LED_1206
  rect 1.27x1.6 smd: 1(-1.524,0) 2(1.524,0)
LQFP_64_402X402_20
  round 1.016 smd: (-6.35,6.35) (6.35,-6.35)
  rect 2.032x0.33 smd: 1(-5.625,3.75) 2(-5.625,3.25) 3(-5.625,2.75) 4(-5.625,2.25) 5(-5.625,1.75) 6(-5.625,1.25) 7(-5.625,0.75) 8(-5.625,0.25) 9(-5.625,-0.25) 10(-5.625,-0.75) 11(-5.625,-1.25) 12(-5.625,-1.75) 13(-5.625,-2.25) 14(-5.625,-2.75) 15(-5.625,-3.25) 16(-5.625,-3.75) 33(5.625,-3.75) 34(5.625,-3.25) 35(5.625,-2.75) 36(5.625,-2.25) 37(5.625,-1.75) 38(5.625,-1.25) 39(5.625,-0.75) 40(5.625,-0.25) 41(5.625,0.25) 42(5.625,0.75) 43(5.625,1.25) 44(5.625,1.75) 45(5.625,2.25) 46(5.625,2.75) 47(5.625,3.25) 48(5.625,3.75)
  rect 0.33x2.032 smd: 17(-3.75,-5.625) 18(-3.25,-5.625) 19(-2.75,-5.625) 20(-2.25,-5.625) 21(-1.75,-5.625) 22(-1.25,-5.625) 23(-0.75,-5.625) 24(-0.25,-5.625) 25(0.25,-5.625) 26(0.75,-5.625) 27(1.25,-5.625) 28(1.75,-5.625) 29(2.25,-5.625) 30(2.75,-5.625) 31(3.25,-5.625) 32(3.75,-5.625) 49(3.75,5.625) 50(3.25,5.625) 51(2.75,5.625) 52(2.25,5.625) 53(1.75,5.625) 54(1.25,5.625) 55(0.75,5.625) 56(0.25,5.625) 57(-0.25,5.625) 58(-0.75,5.625) 59(-1.25,5.625) 60(-1.75,5.625) 61(-2.25,5.625) 62(-2.75,5.625) 63(-3.25,5.625) 64(-3.75,5.625)
MFG125_PLATED
  round 3.556 hole 3.175: 1(0,0)
MSOP_8_118X118_26
  rect 1.575x0.406 smd: 1(-2.225,0.975) 2(-2.225,0.325) 3(-2.225,-0.325) 4(-2.225,-0.975) 5(2.225,-0.975) 6(2.225,-0.325) 7(2.225,0.325) 8(2.225,0.975)
PROBE_POINT_22PAD
  round 0.508 smd: 1(0,0)
QFN20_RGR_P5MM
  custom 0.076x0.076 smd: 1(-1.85,1) 2(-1.85,0.5) 3(-1.85,0) 4(-1.85,-0.5) 5(-1.85,-1) 6(-1,-1.85) 7(-0.5,-1.85) 8(0,-1.85) 9(0.5,-1.85) 10(1,-1.85) 11(1.85,-1) 12(1.85,-0.5) 13(1.85,0) 14(1.85,0.5) 15(1.85,1) 16(1,1.85) 17(0.5,1.85) 18(0,1.85) 19(-0.5,1.85) 20(-1,1.85)
  rect 2.032x2.032 smd: 21(0,0)
QFN20_RGW_P65PITCH
  custom 0.09x0.09 smd: 1(-2.607,1.3) 2(-2.607,0.65) 3(-2.607,0) 4(-2.607,-0.65) 5(-2.607,-1.3) 6(-1.3,-2.607) 7(-0.65,-2.607) 8(0,-2.607) 9(0.65,-2.607) 10(1.3,-2.607) 11(2.607,-1.3) 12(2.607,-0.65) 13(2.607,0) 14(2.607,0.65) 15(2.607,1.3) 16(1.3,2.607) 17(0.65,2.607) 18(0,2.607) 19(-0.65,2.607) 20(-1.3,2.607)
  rect 3.302x3.302 smd: 21(0,0)
QFN_16_124X124_PWRPAD
  rect 0.889x0.305 smd: 1(-1.6,0.749) 2(-1.6,0.249) 3(-1.6,-0.249) 4(-1.6,-0.749) 9(1.6,-0.749) 10(1.6,-0.249) 11(1.6,0.249) 12(1.6,0.749)
  rect 0.305x0.889 smd: 5(-0.749,-1.6) 6(-0.249,-1.6) 7(0.249,-1.6) 8(0.749,-1.6) 13(0.749,1.6) 14(0.249,1.6) 15(-0.249,1.6) 16(-0.749,1.6)
  rect 1.651x1.651 smd: 17(0,0)
QFN_16_124X124_RGT
  oval 0.838x0.279 smd: 1(-1.6,0.749) 2(-1.6,0.249) 3(-1.6,-0.249) 4(-1.6,-0.749) 9(1.6,-0.749) 10(1.6,-0.249) 11(1.6,0.249) 12(1.6,0.749)
  oval 0.279x0.838 smd: 5(-0.749,-1.6) 6(-0.249,-1.6) 7(0.249,-1.6) 8(0.749,-1.6) 13(0.749,1.6) 14(0.249,1.6) 15(-0.249,1.6) 16(-0.749,1.6)
  rect 1.702x1.702 smd: 17(0,0)
QFN_20_183X144_RGY
  rect 0.762x0.356 smd: 1(-2.125,-0.75) 10(2.125,-0.75) 11(2.125,0.75) 20(-2.125,0.75)
  rect 0.356x0.762 smd: 2(-1.75,-1.625) 3(-1.25,-1.625) 4(-0.75,-1.625) 5(-0.25,-1.625) 6(0.25,-1.625) 7(0.75,-1.625) 8(1.25,-1.625) 9(1.75,-1.625) 12(1.75,1.625) 13(1.25,1.625) 14(0.75,1.625) 15(0.25,1.625) 16(-0.25,1.625) 17(-0.75,1.625) 18(-1.25,1.625) 19(-1.75,1.625)
  rect 3.15x2.159 smd: 21(0,0)
QFN_20_197X197_0P65_RGW
  rect 0.991x0.356 smd: 1(-2.607,1.3) 2(-2.607,0.65) 3(-2.607,0) 4(-2.607,-0.65) 5(-2.607,-1.3) 11(2.607,-1.3) 12(2.607,-0.65) 13(2.607,0) 14(2.607,0.65) 15(2.607,1.3)
  rect 0.356x0.991 smd: 6(-1.3,-2.607) 7(-0.65,-2.607) 8(0,-2.607) 9(0.65,-2.607) 10(1.3,-2.607) 16(1.3,2.607) 17(0.65,2.607) 18(0,2.607) 19(-0.65,2.607) 20(-1.3,2.607)
  rect 3.15x3.15 smd: 21(0,0)
QFN_64_360X360_0P50MM_PWRPAD
  oval 1.016x0.305 smd: 1(-4.58,3.753) 2(-4.58,3.252) 3(-4.58,2.752) 4(-4.58,2.252) 5(-4.58,1.751) 6(-4.58,1.251) 7(-4.58,0.751) 8(-4.58,0.25) 9(-4.58,-0.25) 10(-4.58,-0.751) 11(-4.58,-1.251) 12(-4.58,-1.751) 13(-4.58,-2.252) 14(-4.58,-2.752) 15(-4.58,-3.252) 16(-4.58,-3.753) 33(4.58,-3.753) 34(4.58,-3.252) 35(4.58,-2.752) 36(4.58,-2.252) 37(4.58,-1.751) 38(4.58,-1.251) 39(4.58,-0.751) 40(4.58,-0.25) 41(4.58,0.25) 42(4.58,0.751) 43(4.58,1.251) 44(4.58,1.751) 45(4.58,2.252) 46(4.58,2.752) 47(4.58,3.252) 48(4.58,3.753)
  oval 0.305x1.016 smd: 17(-3.753,-4.58) 18(-3.252,-4.58) 19(-2.752,-4.58) 20(-2.252,-4.58) 21(-1.751,-4.58) 22(-1.251,-4.58) 23(-0.751,-4.58) 24(-0.25,-4.58) 25(0.25,-4.58) 26(0.751,-4.58) 27(1.251,-4.58) 28(1.751,-4.58) 29(2.252,-4.58) 30(2.752,-4.58) 31(3.252,-4.58) 32(3.753,-4.58) 49(3.753,4.58) 50(3.252,4.58) 51(2.752,4.58) 52(2.252,4.58) 53(1.751,4.58) 54(1.251,4.58) 55(0.751,4.58) 56(0.25,4.58) 57(-0.25,4.58) 58(-0.751,4.58) 59(-1.251,4.58) 60(-1.751,4.58) 61(-2.252,4.58) 62(-2.752,4.58) 63(-3.252,4.58) 64(-3.753,4.58)
  rect 7.366x7.366 smd: 65(0,0)
